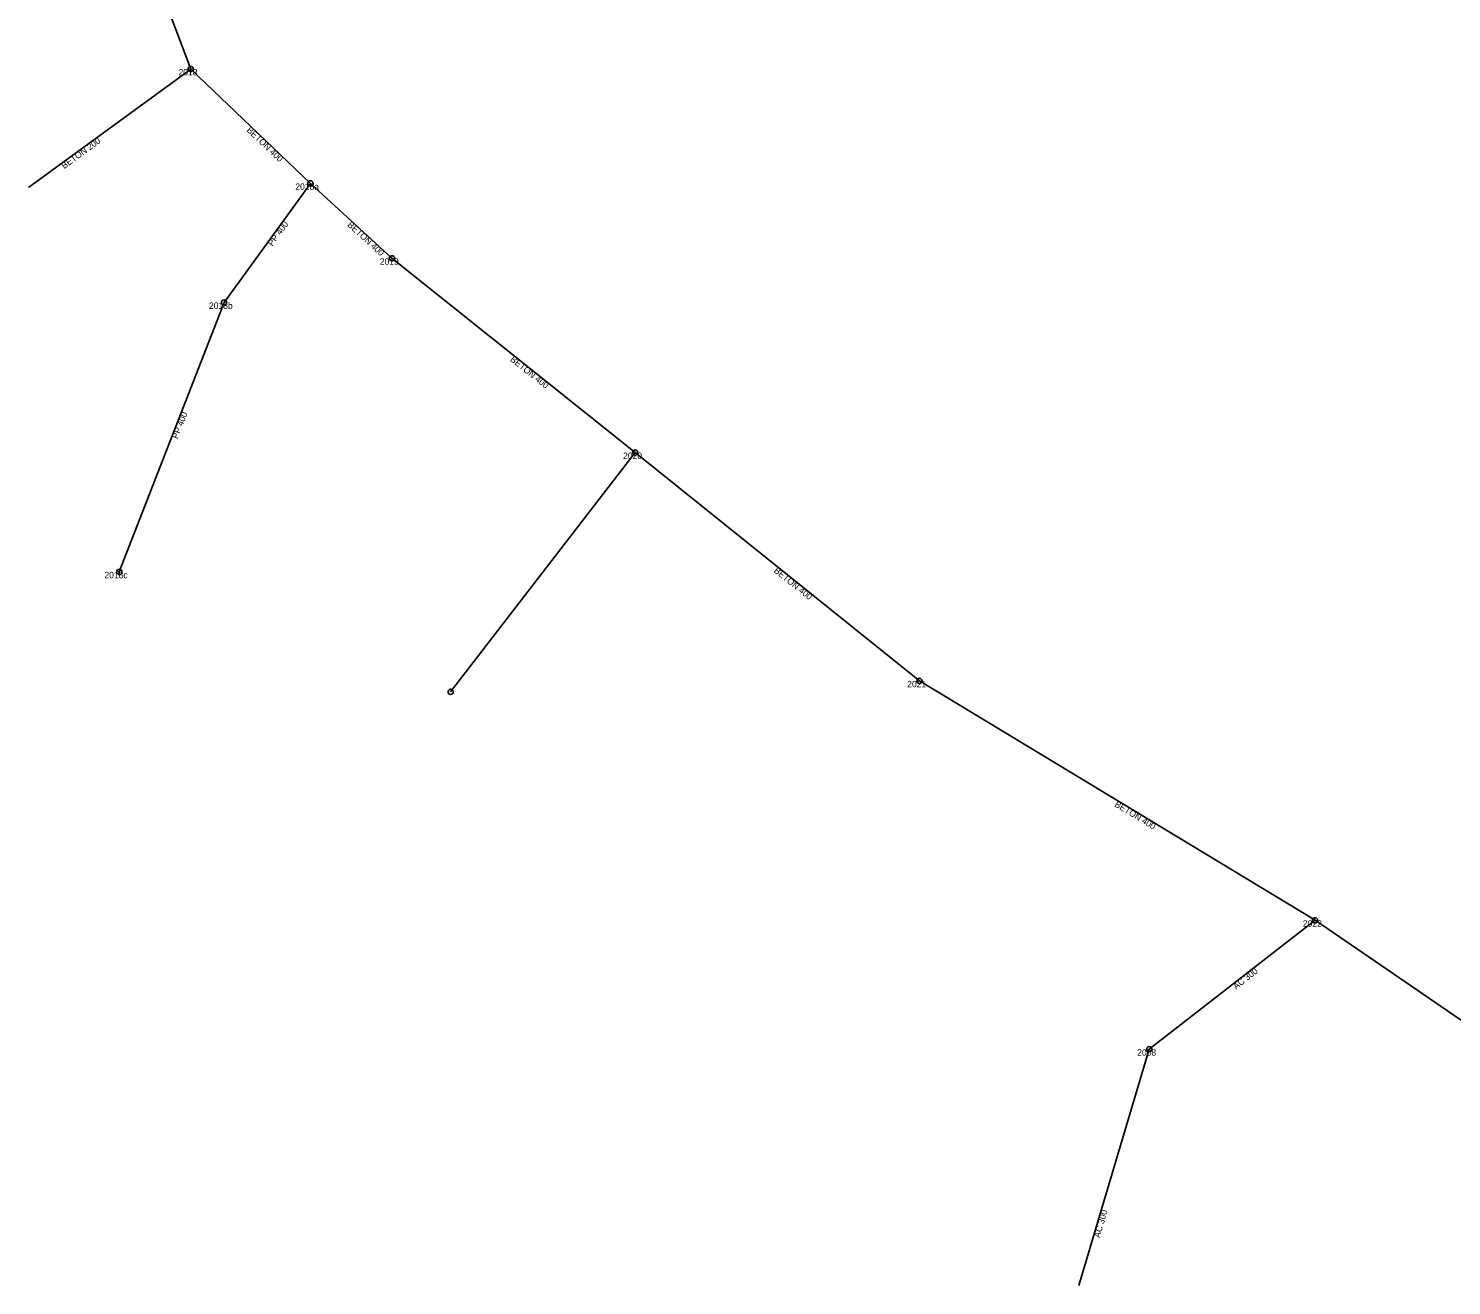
# Model space of a CAD drawing. Extents: x -513135 to -512193, y -1131115 to -1130144.
# Drawn here: x -513104.4 to -512886.6, y -1130617 to -1130424.6 of the extents above; entities that cross this region are included whole.
import ezdxf

# ---------------------------------------------------------------- set-up
doc = ezdxf.new("R2010")
doc.units = 0
for name, color, linetype in [('Default', 7, 'Continuous'), ('MoLevel 1', 7, 'Continuous'), ('MoLevel 2', 7, 'Continuous'), ('MoLevel 4', 7, 'Continuous'), ('MoLevel 41', 7, 'Continuous'), ('MoLevel 42', 7, 'Continuous')]:
    doc.layers.add(name, color=color, linetype=linetype)

# ---------------------------------------------------------------- blocks, each defined once
blk = doc.blocks.new('0.019')
at = {"layer": 'Default'}
blk.add_circle((0, 0), 0.04, dxfattribs=at)

msp = doc.modelspace()

# ---------------------------------------------------------------- linework, layer by layer
at = {"layer": 'MoLevel 1'}
for p, q in [((-513103.42, -1130367.24), (-513079.58, -1130430.77)), ((-513104.4, -1130448.89), (-513079.58, -1130430.77)), ((-513079.58, -1130430.77), (-513061.26, -1130448.27)), ((-513061.26, -1130448.27), (-513074.48, -1130466.5)), ((-513061.26, -1130448.27), (-513048.78, -1130459.74)), ((-513048.78, -1130459.74), (-513011.55, -1130489.47)), ((-513074.48, -1130466.5), (-513090.5, -1130507.73)), ((-512968.06, -1130524.42), (-513011.55, -1130489.47)), ((-513090.5, -1130507.73), (-513090.66, -1130507.76)), ((-513090.5, -1130507.73), (-513090.55, -1130508.22)), ((-512907.52, -1130561.07), (-512968.06, -1130524.42)), ((-512932.88, -1130580.8), (-512907.52, -1130561.07)), ((-512855.5, -1130596.69), (-512907.52, -1130561.07)), ((-512943.66, -1130616.97), (-512932.88, -1130580.8))]:
    msp.add_line(p, q, dxfattribs=at)
at = {"layer": 'MoLevel 4'}
msp.add_line((-513039.8, -1130526.11), (-513011.55, -1130489.47), dxfattribs=at)

# ---------------------------------------------------------------- block references
at = {"layer": 'MoLevel 2', "xscale": 10, "yscale": 10}
for p in [(-513079.58, -1130430.77), (-513061.26, -1130448.27), (-513048.78, -1130459.74), (-513074.48, -1130466.5), (-513011.55, -1130489.47), (-513090.5, -1130507.73), (-512968.06, -1130524.42), (-513039.8, -1130526.11), (-512907.52, -1130561.07), (-512932.88, -1130580.8)]:
    msp.add_blockref('0.019', p, dxfattribs=at)

# ---------------------------------------------------------------- texts
at = {"layer": 'MoLevel 41'}
for s, rotation, p in [('BETON 400', 316.3114, (-513071.09, -1130440.23)), ('BETON 200', 36.134, (-513098.94, -1130446.11)), ('PP 400', 54.0512, (-513067.08, -1130457.96)), ('BETON 400', 317.4148, (-513055.68, -1130454.72)), ('BETON 400', 321.3909, (-513030.77, -1130475.37)), ('PP 400', 68.7663, (-513081.58, -1130487.47)), ('BETON 400', 321.2135, (-512990.42, -1130507.7)), ('BETON 400', 328.8099, (-512938.29, -1130543.58)), ('AC 300', 37.8828, (-512919.6, -1130571.7)), ('AC 300', 73.4106, (-512940.48, -1130609.72))]:
    msp.add_text(s, height=0.975, rotation=rotation, dxfattribs=at).set_placement(p)
at = {"layer": 'MoLevel 42'}
for s, p in [('2018', (-513081.44, -1130431.75)), ('2018a', (-513063.56, -1130449.25)), ('2019', (-513050.64, -1130460.72)), ('2018b', (-513076.78, -1130467.48)), ('2020', (-513013.41, -1130490.45)), ('2018c', (-513092.78, -1130508.71)), ('2021', (-512969.92, -1130525.4)), ('2022', (-512909.38, -1130562.05)), ('2068', (-512934.74, -1130581.78))]:
    msp.add_text(s, height=0.975, dxfattribs=at).set_placement(p)

doc.saveas('drawing.dxf')
